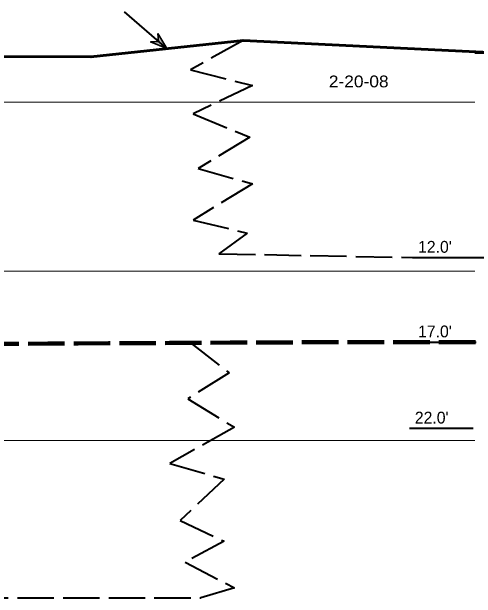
# Model space of a CAD drawing. Extents: x -76 to 974, y -1080 to -735.
# Drawn here: x 765.06 to 792.54, y -961.41 to -926.75 of the extents above; entities that cross this region are included whole.
import ezdxf
from ezdxf.enums import TextEntityAlignment as Align

# ---------------------------------------------------------------- set-up
doc = ezdxf.new("R2010")
doc.units = 0
doc.header["$LTSCALE"] = 0.36
doc.linetypes.add('LONG_DASHED', pattern=[7.5, 6, -1.5])
for name, color, linetype, lineweight in [('10', 7, 'Continuous', 35), ('27', 7, 'Continuous', 40), ('28', 7, 'LONG_DASHED', 60), ('7', 7, 'Continuous', 13)]:
    doc.layers.add(name, color=color, linetype=linetype, lineweight=lineweight)

msp = doc.modelspace()

# ---------------------------------------------------------------- hatches: boundary and pattern name
at = {"layer": '10'}
msp.add_hatch(color=256, dxfattribs=at).paths.add_polyline_path([(773.7079, -928.0326), (774.2455, -928.9302), (773.2771, -928.5348), (773.7435, -928.499)])

# ---------------------------------------------------------------- linework, layer by layer
msp.add_lwpolyline([(773.7079, -928.0326), (774.2455, -928.9302), (773.2771, -928.5348), (773.7435, -928.499)], close=True, dxfattribs=at)
at = {"layer": '27'}
for p, q in [((774.2457, -928.93), (771.7253, -926.7477)), ((792.4513, -929.179), (795.0402, -929.179)), ((788.7727, -941.2678), (792.5401, -941.2678)), ((788.7727, -946.2678), (792.5401, -946.2678)), ((788.5822, -951.3602), (792.3496, -951.3602))]:
    msp.add_line(p, q, dxfattribs=at)
at = {"layer": '28', "linetype": 'Continuous'}
msp.add_lwpolyline([(746.2457, -928.99), (758.7457, -929.3789), (769.7457, -929.42), (778.7457, -928.44), (793.7457, -929.179), (798.7457, -929.04)], dxfattribs=at)
at = {"layer": '28', "lineweight": 40}
for points in [[(778.7457, -928.44), (775.6312, -930.1865), (779.3021, -931.1049), (775.7842, -932.7886), (779.1491, -934.1662), (776.0901, -936.0029), (779.3021, -936.9213), (775.7842, -939.0642), (778.9962, -939.8296), (777.3137, -941.0541)], [(777.3137, -941.0541), (788.7727, -941.2678), (792.5402, -941.2678), (795.0402, -941.2678), (808.3629, -941.2678)], [(775.6316, -946.3161), (777.9255, -948.0951), (775.4783, -949.6257), (778.2314, -951.3094), (774.4076, -953.4523), (777.6196, -954.3707), (775.0194, -956.8198), (777.6196, -958.0443), (775.3253, -959.2688), (778.2314, -960.7994), (776.2431, -961.3789)], [(743.6643, -961.4117), (753.6395, -961.3789), (757.4069, -961.3789), (759.9958, -961.3789), (776.2431, -961.3789)]]:
    msp.add_lwpolyline(points, dxfattribs=at)
at = {"layer": '28', "lineweight": 100}
msp.add_spline([(744.4291, -946.2583), (753.6395, -946.3789), (757.4958, -946.3789), (759.9958, -946.3789), (788.7727, -946.2678), (792.5401, -946.2678), (795.0402, -946.2678), (808.8218, -946.2678)], degree=3, dxfattribs=at)
at = {"layer": '7'}
for p, q in [((759.9958, -932.09), (792.4513, -932.09)), ((759.9958, -942.09), (792.4513, -942.09)), ((759.9958, -952.09), (792.4513, -952.09))]:
    msp.add_line(p, q, dxfattribs=at)

# ---------------------------------------------------------------- texts
at = {"layer": '27', "width": 1.1}
msp.add_text('2-20-08', height=0.6976, dxfattribs=at).set_placement((785.5859, -931.2162), align=Align.CENTER)
at = {"layer": '27'}
for s, p in [("12.0'", (789.0968, -940.9914)), ("17.0'", (789.0968, -945.9914)), ("22.0'", (788.9063, -951.0838))]:
    msp.add_text(s, height=0.6976, dxfattribs=at).set_placement(p)

doc.saveas('drawing.dxf')
